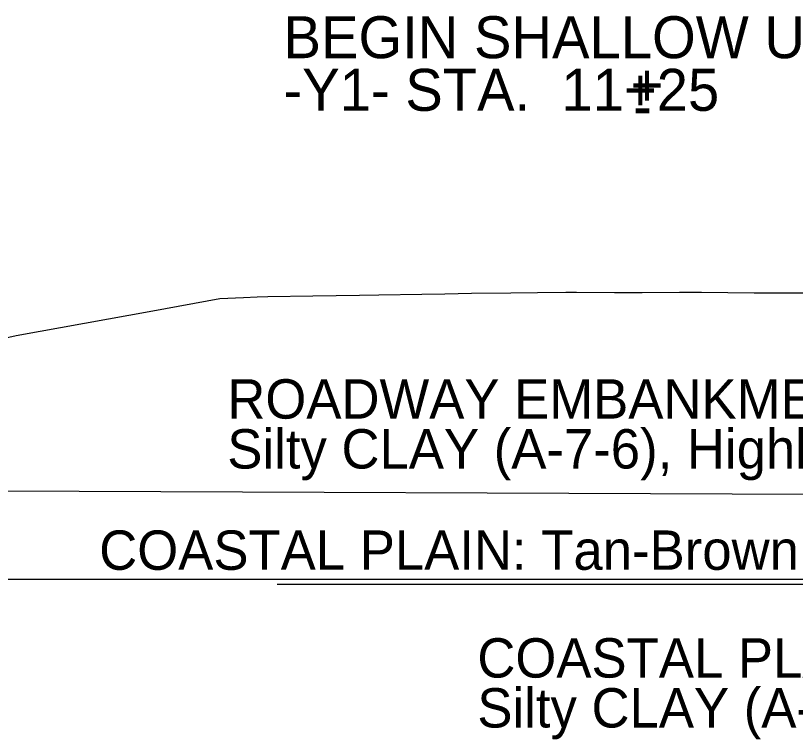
# Model space of a CAD drawing. Extents: x -516 to 303, y -10 to 5017.
# Drawn here: x 109.71 to 139.4, y 993.9 to 1021.47 of the extents above; entities that cross this region are included whole.
import ezdxf

# ---------------------------------------------------------------- set-up
doc = ezdxf.new("R2010")
doc.units = 0
for name, color, linetype in [('Exist Cross Section Cell', 7, 'Continuous'), ('Exist XS Ground Line', 7, 'Continuous'), ('Prop Road Sect_ Material - Contact (General - Major)', 7, 'Continuous'), ('Prop Road Sect_ Material - Contact (General - Minor)', 7, 'Continuous'), ('Prop Road Sect_ Material - Tx (Composite Desc)', 7, 'Continuous'), ('Prop Road Sect_ Recs - UC Shallow (Tx)', 7, 'Continuous')]:
    doc.layers.add(name, color=color, linetype=linetype)

msp = doc.modelspace()

# ---------------------------------------------------------------- linework, layer by layer
at = {"layer": 'Exist Cross Section Cell'}
msp.add_line((0, 1000), (150, 1000), dxfattribs=at)
at = {"layer": 'Exist XS Ground Line'}
msp.add_lwpolyline([(107.556, 1008.802), (109.734, 1009.284), (114.927, 1010.225), (117.489, 1010.694), (118.387, 1010.734), (118.902, 1010.757), (119.314, 1010.763), (121.021, 1010.795), (122.807, 1010.823), (123.543, 1010.835), (125.172, 1010.861), (126.055, 1010.875), (127.062, 1010.889), (128.561, 1010.908), (129.576, 1010.918), (130.655, 1010.93), (131.065, 1010.927), (132.508, 1010.916), (133.563, 1010.919), (134.99, 1010.931), (135.827, 1010.937), (137.833, 1010.914), (138.752, 1010.904), (140.362, 1010.91)], dxfattribs=at)
at = {"layer": 'Prop Road Sect_ Material - Contact (General - Major)'}
msp.add_line((37.709, 1003.659), (189.69, 1003.027), dxfattribs=at)
at = {"layer": 'Prop Road Sect_ Material - Contact (General - Minor)'}
msp.add_line((213.997, 999.8), (119.667, 999.8), dxfattribs=at)

# ---------------------------------------------------------------- texts
at = {"layer": 'Prop Road Sect_ Material - Tx (Composite Desc)'}
for s, p in [('ROADWAY EMBANKMENT: Brown, Medium Stiff to Stiff, ', (117.769, 1006.116)), ('Silty CLAY (A-7-6), Highly Plastic, Trace Gravel, Moist', (117.769, 1004.215)), ('COASTAL PLAIN: Tan-Brown, Medium Stiff, Sandy SILT (A-4), Moist (Black Creek Formation)', (112.891, 1000.358)), ('COASTAL PLAIN: Orange-Brown to Gray, Medium Stiff, ', (127.289, 996.252)), ('Silty CLAY (A-7-6), Highly Plastic, Moist (Black Creek Formation)', (127.289, 994.351))]:
    msp.add_text(s, height=1.5, dxfattribs=at).set_placement(p)
at = {"layer": 'Prop Road Sect_ Recs - UC Shallow (Tx)'}
for s, p in [('BEGIN SHALLOW UNDERCUT FOR AGGREGATE SUBGRADE', (119.909, 1019.844)), ('-Y1- STA.  11+25', (119.909, 1017.84)), ('+', (133.119, 1018.027)), ('-', (133.226, 1017.221))]:
    msp.add_text(s, height=1.6, dxfattribs=at).set_placement(p)

doc.saveas('drawing.dxf')
